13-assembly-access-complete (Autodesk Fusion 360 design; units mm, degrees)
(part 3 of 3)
extrude "Extrude2" cut sketch "E Rear Bearing Cap Bolt seed" profile of C1 along normal blind 3 (= "capThickness")
circular_pattern "C-Pattern1" TotalAngle 360
chamfer "Chamfer1" distance 0.3 (= "bedRelief")
work_plane "WorkPlane1" AlongDistance -29 (= "hubFace - adapterThickness") ExtraOffset 0
sketch "F Adapter Flange sketch" plane through (-20.5061, -20.5061, 0) normal (0.7071, 0.7071, 0) x axis (0, 0, 1)
  circle C1 centre (0, 0) radius 38
  dimension "d967" diameter C1 = 76 (= "mountOD")
extrude "Extrude1" new body sketch "F Adapter Flange sketch" along normal blind 6 (= "adapterThickness")
work_plane "WorkPlane2" AlongDistance -23 (= "hubFace") ExtraOffset 0
sketch "F Centering Pilot sketch" plane through (-16.2635, -16.2635, 0) normal (0.7071, 0.7071, 0) x axis (0, 0, 1)
  circle C1 centre (0, 0) radius 25
  circle C2 centre (0, 0) radius 17
  dimension "d972" diameter C1 = 50 (= "pilotDiameter")
  dimension "d973" diameter C2 = 34 (= "pilotInside")
extrude "Extrude2" add sketch "F Centering Pilot sketch" along normal blind 2 (= "pilotHeight")
work_plane "WorkPlane3" AlongDistance -29 (= "hubFace - adapterThickness") ExtraOffset 0
sketch "F Shaft Clearance sketch" plane through (-20.5061, -20.5061, 0) normal (0.7071, 0.7071, 0) x axis (0, 0, 1)
  circle C1 centre (0, 0) radius 4.25
  dimension "d978" diameter C1 = 8.5 (= "shaftClearance")
extrude "Extrude3" cut sketch "F Shaft Clearance sketch" along normal blind 6 (= "adapterThickness")
work_plane "WorkPlane4" AlongDistance -29 (= "hubFace - adapterThickness") ExtraOffset 0
sketch "F Mount Holes" plane through (-20.5061, -20.5061, 0) normal (0.7071, 0.7071, 0) x axis (0, 0, 1)
  circle C1 centre (22.6274, 22.6274) radius 2.15
  circle C2 centre (-22.6274, 22.6274) radius 2.15
  circle C3 centre (-22.6274, -22.6274) radius 2.15
  circle C4 centre (22.6274, -22.6274) radius 2.15
  point P1 (0, 0)
  point P2 (22.6274, 22.6274)
  point P3 (-22.6274, 22.6274)
  point P4 (-22.6274, -22.6274)
  point P5 (22.6274, -22.6274)
  dimension "d983" distance P1 P2 = 22.6274 (= "abs(mountCircle / ( 2 * sqrt(2) ))")
  dimension "d984" distance P1 P2 = 22.6274 (= "abs(mountCircle / ( 2 * sqrt(2) ))")
  dimension "d985" diameter C1 = 4.3 (= "m4Clearance")
  dimension "d986" distance P1 P3 = 22.6274 (= "abs(-mountCircle / ( 2 * sqrt(2) ))")
  dimension "d987" distance P1 P3 = 22.6274 (= "abs(mountCircle / ( 2 * sqrt(2) ))")
  dimension "d988" diameter C2 = 4.3 (= "m4Clearance")
  dimension "d989" distance P1 P4 = 22.6274 (= "abs(-mountCircle / ( 2 * sqrt(2) ))")
  dimension "d990" distance P1 P4 = 22.6274 (= "abs(-mountCircle / ( 2 * sqrt(2) ))")
  dimension "d991" diameter C3 = 4.3 (= "m4Clearance")
  dimension "d992" distance P1 P5 = 22.6274 (= "abs(mountCircle / ( 2 * sqrt(2) ))")
  dimension "d993" distance P1 P5 = 22.6274 (= "abs(-mountCircle / ( 2 * sqrt(2) ))")
  dimension "d994" diameter C4 = 4.3 (= "m4Clearance")
extrude "Extrude4" cut sketch "F Mount Holes" along normal blind 6 (= "adapterThickness")
sketch "F Compression Sleeve Holes" plane through (-20.5061, -20.5061, 0) normal (0.7071, 0.7071, 0) x axis (0, 0, 1)
  line L1 (11.3137, 0) -> (0, 0)
  line L2 (0, 11.3137) -> (0, 0)
  line L3 (-11.3137, 0) -> (0, 0)
  line L4 (0, -11.3137) -> (0, 0)
  circle C1 centre (11.3137, 0) radius 4.1
  circle C2 centre (0, 11.3137) radius 4.1
  circle C3 centre (-11.3137, 0) radius 4.1
  circle C4 centre (0, -11.3137) radius 4.1
  point P1 (0, 0)
  point P2 (11.3137, 0)
  point P3 (0, 11.3137)
  point P5 (0, -11.3137)
  horizontal L1
  vertical L2
  horizontal L3
  vertical L4
  dimension "d997" distance P1 P2 = 11.3137 (= "abs(hubHoleSpacing / sqrt(2))")
  dimension "d998" diameter C1 = 8.2 (= "sleeveOD + sleeveAllowance")
  dimension "d999" distance P1 P3 = 11.3137 (= "abs(hubHoleSpacing / sqrt(2))")
  dimension "d1000" diameter C2 = 8.2 (= "sleeveOD + sleeveAllowance")
  dimension "d59" = 150 (= "bodyWidth")
  dimension "d1002" diameter C3 = 8.2 (= "sleeveOD + sleeveAllowance")
  dimension "d1003" distance P1 P5 = 11.3137 (= "abs(-hubHoleSpacing / sqrt(2))")
  dimension "d1004" diameter C4 = 8.2 (= "sleeveOD + sleeveAllowance")
  dimension "d1001" distance = 11.3137 (= "abs(-hubHoleSpacing / sqrt(2))")
extrude "Extrude5" cut sketch "F Compression Sleeve Holes" profile of C1 C2 C3 C4 along normal blind 6 (= "adapterThickness")
chamfer "Chamfer1" distance 0.4 (= "entryChamfer")
chamfer "Chamfer2" distance 0.3 (= "bedRelief")
work_plane "WorkPlane1" AlongDistance 0.5 (= "qFront") ExtraOffset 0
sketch "Front 608 sketch" plane through (0.3536, 0.3536, 0) normal (0.7071, 0.7071, 0) x axis (0, 0, 1)
  circle C1 centre (0, 0) radius 11
  circle C2 centre (0, 0) radius 4
  dimension "d1011" diameter C1 = 22 (= "bearingOD")
  dimension "d1012" diameter C2 = 8 (= "bearingID")
extrude "Extrude1" new body sketch "Front 608 sketch" along normal blind 7 (= "bearingWidth")
work_plane "WorkPlane2" AlongDistance 25.6 (= "qRearBearing") ExtraOffset 0
sketch "Rear 608 sketch" plane through (18.1019, 18.1019, 0) normal (0.7071, 0.7071, 0) x axis (0, 0, 1)
  circle C1 centre (0, 0) radius 11
  circle C2 centre (0, 0) radius 4
  dimension "d1017" diameter C1 = 22 (= "bearingOD")
  dimension "d1018" diameter C2 = 8 (= "bearingID")
extrude "Extrude2" new body sketch "Rear 608 sketch" along normal blind 7 (= "bearingWidth")
work_plane "WorkPlane1" AlongDistance -24 ExtraOffset 0
sketch "Metal Shaft sketch" plane through (-16.9706, -16.9706, 0) normal (0.7071, 0.7071, 0) x axis (0, 0, 1)
  circle C1 centre (0, 0) radius 4
  dimension "d1023" diameter C1 = 8
extrude "Extrude1" new body sketch "Metal Shaft sketch" along normal blind 60
work_plane "WorkPlane1" AlongDistance -3.5 (= "qFront - 4 mm") ExtraOffset 0
sketch "Front Inner Ring Spacer sketch" plane through (-2.4749, -2.4749, 0) normal (0.7071, 0.7071, 0) x axis (0, 0, 1)
  circle C1 centre (0, 0) radius 5
  circle C2 centre (0, 0) radius 4
  dimension "d1028" diameter C1 = 10
  dimension "d1029" diameter C2 = 8
extrude "Extrude1" new body sketch "Front Inner Ring Spacer sketch" along normal blind 4
work_plane "WorkPlane2" AlongDistance 7.5 (= "qFront + bearingWidth") ExtraOffset 0
sketch "Rear Inner Ring Spacer sketch" plane through (5.3033, 5.3033, 0) normal (0.7071, 0.7071, 0) x axis (0, 0, 1)
  circle C1 centre (0, 0) radius 5
  circle C2 centre (0, 0) radius 4
  dimension "d1034" diameter C1 = 10
  dimension "d1035" diameter C2 = 8
extrude "Extrude2" new body sketch "Rear Inner Ring Spacer sketch" along normal blind 4
work_plane "WorkPlane1" AlongDistance -12.5 (= "qFront - 13 mm") ExtraOffset 0
sketch "Front Collar Maximum Envelope sketch" plane through (-8.8388, -8.8388, 0) normal (0.7071, 0.7071, 0) x axis (0, 0, 1)
  circle C1 centre (0, 0) radius 11.2
  circle C2 centre (0, 0) radius 4
  dimension "d1040" diameter C1 = 22.4
  dimension "d1041" diameter C2 = 8
extrude "Extrude1" new body sketch "Front Collar Maximum Envelope sketch" along normal blind 9
work_plane "WorkPlane2" AlongDistance 11.5 (= "qFront + bearingWidth + 4 mm") ExtraOffset 0
sketch "Rear Collar Maximum Envelope sketch" plane through (8.1317, 8.1317, 0) normal (0.7071, 0.7071, 0) x axis (0, 0, 1)
  circle C1 centre (0, 0) radius 11.2
  circle C2 centre (0, 0) radius 4
  dimension "d1046" diameter C1 = 22.4
  dimension "d1047" diameter C2 = 8
extrude "Extrude2" new body sketch "Rear Collar Maximum Envelope sketch" along normal blind 9
work_plane "WorkPlane1" AlongDistance 0 ExtraOffset 0
sketch "Spacer Pattern Axis" plane through (0, 0, 0) normal (0.7071, 0.7071, 0) x axis (0, 0, 1)
  circle C1 centre (0, 0) radius 0.5
  dimension "d1052" diameter C1 = 1
work_plane "WorkPlane2" AlongDistance 10.6 (= "qFrontBack") ExtraOffset 0
sketch "Support Spacer OD" plane through (7.4953, 7.4953, 0) normal (0.7071, 0.7071, 0) x axis (0, 0, 1)
  line L1 (17, 0) -> (0, 0)
  circle C1 centre (17, 0) radius 3
  circle C2 centre (17, 0) radius 1.6
  point P1 (0, 0)
  point P2 (17, 0)
  horizontal L1
  dimension "d1055" distance P1 P2 = 17 (= "supportCircle / 2")
  dimension "d1056" diameter C1 = 6 (= "supportSpacerOD")
  dimension "d1057" diameter C2 = 3.2
extrude "Extrude1" new body sketch "Support Spacer OD" profile of C1 C2 along normal blind 12 (= "supportSpacer")
circular_pattern "C-Pattern1" TotalAngle 360
work_plane "WorkPlane1" AlongDistance -29 (= "hubFace - adapterThickness") ExtraOffset 0
sketch "Sleeve 1 Outer" plane through (-20.5061, -20.5061, 0) normal (0.7071, 0.7071, 0) x axis (0, 0, 1)
  line L1 (11.3137, 0) -> (0, 0)
  circle C1 centre (11.3137, 0) radius 4
  circle C2 centre (11.3137, 0) radius 2.15
  point P1 (0, 0)
  point P2 (11.3137, 0)
  horizontal L1
  dimension "d1064" distance P1 P2 = 11.3137 (= "abs(hubHoleSpacing / sqrt(2))")
  dimension "d1065" diameter C1 = 8 (= "sleeveOD")
  dimension "d1066" diameter C2 = 4.3
extrude "Extrude1" new body sketch "Sleeve 1 Outer" profile of C1 C2 along normal blind 6 (= "adapterThickness")
work_plane "WorkPlane2" AlongDistance -29 (= "hubFace - adapterThickness") ExtraOffset 0
sketch "Sleeve 2 Outer" plane through (-20.5061, -20.5061, 0) normal (0.7071, 0.7071, 0) x axis (0, 0, 1)
  line L1 (0, 11.3137) -> (0, 0)
  circle C1 centre (0, 11.3137) radius 4
  circle C2 centre (0, 11.3137) radius 2.15
  point P1 (0, 0)
  point P2 (0, 11.3137)
  vertical L1
  dimension "d1071" distance P1 P2 = 11.3137 (= "abs(hubHoleSpacing / sqrt(2))")
  dimension "d1072" diameter C1 = 8 (= "sleeveOD")
  dimension "d1073" diameter C2 = 4.3
extrude "Extrude2" new body sketch "Sleeve 2 Outer" profile of C1 C2 along normal blind 6 (= "adapterThickness")
work_plane "WorkPlane3" AlongDistance -29 (= "hubFace - adapterThickness") ExtraOffset 0
sketch "Sleeve 3 Outer" plane through (-20.5061, -20.5061, 0) normal (0.7071, 0.7071, 0) x axis (0, 0, 1)
  line L1 (-11.3137, 0) -> (0, 0)
  circle C1 centre (-11.3137, 0) radius 4
  circle C2 centre (-11.3137, 0) radius 2.15
  point P1 (0, 0)
  point P2 (-11.3137, 0)
  horizontal L1
  dimension "d1078" distance P1 P2 = 11.3137 (= "abs(-hubHoleSpacing / sqrt(2))")
  dimension "d1079" diameter C1 = 8 (= "sleeveOD")
  dimension "d1080" diameter C2 = 4.3
extrude "Extrude3" new body sketch "Sleeve 3 Outer" profile of C1 C2 along normal blind 6 (= "adapterThickness")
work_plane "WorkPlane4" AlongDistance -29 (= "hubFace - adapterThickness") ExtraOffset 0
sketch "Sleeve 4 Outer" plane through (-20.5061, -20.5061, 0) normal (0.7071, 0.7071, 0) x axis (0, 0, 1)
  line L1 (0, -11.3137) -> (0, 0)
  circle C1 centre (0, -11.3137) radius 4
  circle C2 centre (0, -11.3137) radius 2.15
  point P1 (0, 0)
  point P2 (0, -11.3137)
  vertical L1
  dimension "d1085" distance P1 P2 = 11.3137 (= "abs(-hubHoleSpacing / sqrt(2))")
  dimension "d1086" diameter C1 = 8 (= "sleeveOD")
  dimension "d1087" diameter C2 = 4.3
extrude "Extrude4" new body sketch "Sleeve 4 Outer" profile of C1 C2 along normal blind 6 (= "adapterThickness")
work_plane "WorkPlane1" AlongDistance -23 (= "hubFace") ExtraOffset 0
sketch "Sonic Hub Body sketch" plane through (-16.2635, -16.2635, 0) normal (0.7071, 0.7071, 0) x axis (0, 0, 1)
  circle C1 centre (0, 0) radius 16
  circle C2 centre (0, 0) radius 4
  dimension "d1092" diameter C1 = 32
  dimension "d1093" diameter C2 = 8
extrude "Extrude1" new body sketch "Sonic Hub Body sketch" along normal blind 8
work_plane "WorkPlane2" AlongDistance -15 (= "hubFace + 8 mm") ExtraOffset 0
sketch "Sonic Hub Pilot sketch" plane through (-10.6066, -10.6066, 0) normal (0.7071, 0.7071, 0) x axis (0, 0, 1)
  circle C1 centre (0, 0) radius 7
  circle C2 centre (0, 0) radius 4
  dimension "d1098" diameter C1 = 14
  dimension "d1099" diameter C2 = 8
extrude "Extrude2" add sketch "Sonic Hub Pilot sketch" along normal blind 2
work_plane "WorkPlane3" AlongDistance -23 (= "hubFace") ExtraOffset 0
sketch "Hub M4 Thread Envelopes" plane through (-16.2635, -16.2635, 0) normal (0.7071, 0.7071, 0) x axis (0, 0, 1)
  line L1 (11.3137, 0) -> (0, 0)
  line L2 (0, 11.3137) -> (0, 0)
  line L3 (-11.3137, 0) -> (0, 0)
  line L4 (0, -11.3137) -> (0, 0)
  circle C1 centre (11.3137, 0) radius 2.15
  circle C2 centre (0, 11.3137) radius 2.15
  circle C3 centre (-11.3137, 0) radius 2.15
  circle C4 centre (0, -11.3137) radius 2.15
  point P1 (0, 0)
  point P2 (11.3137, 0)
  point P3 (0, 11.3137)
  point P5 (0, -11.3137)
  horizontal L1
  vertical L2
  horizontal L3
  vertical L4
  dimension "d1104" distance P1 P2 = 11.3137 (= "abs(hubHoleSpacing / sqrt(2))")
  dimension "d1105" diameter C1 = 4.3
  dimension "d1106" distance P1 P3 = 11.3137 (= "abs(hubHoleSpacing / sqrt(2))")
  dimension "d1107" diameter C2 = 4.3
  dimension "d59" = 150 (= "bodyWidth")
  dimension "d1109" diameter C3 = 4.3
  dimension "d1110" distance P1 P5 = 11.3137 (= "abs(-hubHoleSpacing / sqrt(2))")
  dimension "d1111" diameter C4 = 4.3
  dimension "d1108" distance = 11.3137 (= "abs(-hubHoleSpacing / sqrt(2))")
extrude "Extrude3" cut sketch "Hub M4 Thread Envelopes" profile of C1 C2 C3 C4 along normal blind 8
work_plane "WorkPlane1" AlongDistance -30 (= "hubFace - adapterThickness - 1 mm") ExtraOffset 0
sketch "Hub Screw 1 Profile" plane through (-21.2132, -21.2132, 0) normal (0.7071, 0.7071, 0) x axis (0, 0, 1)
  line L1 (11.3137, 0) -> (0, 0)
  circle C1 centre (11.3137, 0) radius 2
  point P1 (0, 0)
  point P2 (11.3137, 0)
  horizontal L1
  dimension "d1116" distance P1 P2 = 11.3137 (= "abs(hubHoleSpacing / sqrt(2))")
  dimension "d1117" diameter C1 = 4
extrude "Extrude1" new body sketch "Hub Screw 1 Profile" profile of C1 along normal blind 12
work_plane "WorkPlane2" AlongDistance -34 (= "hubFace - adapterThickness - 5 mm") ExtraOffset 0
sketch "Hub Screw Head 1 Profile" plane through (-24.0416, -24.0416, 0) normal (0.7071, 0.7071, 0) x axis (0, 0, 1)
  line L1 (11.3137, 0) -> (0, 0)
  circle C1 centre (11.3137, 0) radius 3.5
  point P1 (0, 0)
  point P2 (11.3137, 0)
  horizontal L1
  dimension "d1122" distance P1 P2 = 11.3137 (= "abs(hubHoleSpacing / sqrt(2))")
  dimension "d1123" diameter C1 = 7
extrude "Extrude2" new body sketch "Hub Screw Head 1 Profile" profile of C1 along normal blind 4
work_plane "WorkPlane3" AlongDistance -30 (= "hubFace - adapterThickness - 1 mm") ExtraOffset 0
sketch "Hub Washer 1 Outer" plane through (-21.2132, -21.2132, 0) normal (0.7071, 0.7071, 0) x axis (0, 0, 1)
  line L1 (11.3137, 0) -> (0, 0)
  circle C1 centre (11.3137, 0) radius 6
  circle C2 centre (11.3137, 0) radius 2.15
  point P1 (0, 0)
  point P2 (11.3137, 0)
  horizontal L1
  dimension "d1128" distance P1 P2 = 11.3137 (= "abs(hubHoleSpacing / sqrt(2))")
  dimension "d1129" diameter C1 = 12
  dimension "d1130" diameter C2 = 4.3
extrude "Extrude3" new body sketch "Hub Washer 1 Outer" profile of C1 C2 along normal blind 1
work_plane "WorkPlane4" AlongDistance -30 (= "hubFace - adapterThickness - 1 mm") ExtraOffset 0
sketch "Hub Screw 2 Profile" plane through (-21.2132, -21.2132, 0) normal (0.7071, 0.7071, 0) x axis (0, 0, 1)
  line L1 (0, 11.3137) -> (0, 0)
  circle C1 centre (0, 11.3137) radius 2
  point P1 (0, 0)
  point P2 (0, 11.3137)
  vertical L1
  dimension "d1135" distance P1 P2 = 11.3137 (= "abs(hubHoleSpacing / sqrt(2))")
  dimension "d1136" diameter C1 = 4
extrude "Extrude4" new body sketch "Hub Screw 2 Profile" profile of C1 along normal blind 12
work_plane "WorkPlane5" AlongDistance -34 (= "hubFace - adapterThickness - 5 mm") ExtraOffset 0
sketch "Hub Screw Head 2 Profile" plane through (-24.0416, -24.0416, 0) normal (0.7071, 0.7071, 0) x axis (0, 0, 1)
  line L1 (0, 11.3137) -> (0, 0)
  circle C1 centre (0, 11.3137) radius 3.5
  point P1 (0, 0)
  point P2 (0, 11.3137)
  vertical L1
  dimension "d1141" distance P1 P2 = 11.3137 (= "abs(hubHoleSpacing / sqrt(2))")
  dimension "d1142" diameter C1 = 7
extrude "Extrude5" new body sketch "Hub Screw Head 2 Profile" profile of C1 along normal blind 4
work_plane "WorkPlane6" AlongDistance -30 (= "hubFace - adapterThickness - 1 mm") ExtraOffset 0
sketch "Hub Washer 2 Outer" plane through (-21.2132, -21.2132, 0) normal (0.7071, 0.7071, 0) x axis (0, 0, 1)
  line L1 (0, 11.3137) -> (0, 0)
  circle C1 centre (0, 11.3137) radius 6
  circle C2 centre (0, 11.3137) radius 2.15
  point P1 (0, 0)
  point P2 (0, 11.3137)
  vertical L1
  dimension "d1147" distance P1 P2 = 11.3137 (= "abs(hubHoleSpacing / sqrt(2))")
  dimension "d1148" diameter C1 = 12
  dimension "d1149" diameter C2 = 4.3
extrude "Extrude6" new body sketch "Hub Washer 2 Outer" profile of C1 C2 along normal blind 1
work_plane "WorkPlane7" AlongDistance -30 (= "hubFace - adapterThickness - 1 mm") ExtraOffset 0
sketch "Hub Screw 3 Profile" plane through (-21.2132, -21.2132, 0) normal (0.7071, 0.7071, 0) x axis (0, 0, 1)
  line L1 (-11.3137, 0) -> (0, 0)
  circle C1 centre (-11.3137, 0) radius 2
  point P1 (0, 0)
  point P2 (-11.3137, 0)
  horizontal L1
  dimension "d1154" distance P1 P2 = 11.3137 (= "abs(-hubHoleSpacing / sqrt(2))")
  dimension "d1155" diameter C1 = 4
extrude "Extrude7" new body sketch "Hub Screw 3 Profile" profile of C1 along normal blind 12
work_plane "WorkPlane8" AlongDistance -34 (= "hubFace - adapterThickness - 5 mm") ExtraOffset 0
sketch "Hub Screw Head 3 Profile" plane through (-24.0416, -24.0416, 0) normal (0.7071, 0.7071, 0) x axis (0, 0, 1)
  line L1 (-11.3137, 0) -> (0, 0)
  circle C1 centre (-11.3137, 0) radius 3.5
  point P1 (0, 0)
  point P2 (-11.3137, 0)
  horizontal L1
  dimension "d1160" distance P1 P2 = 11.3137 (= "abs(-hubHoleSpacing / sqrt(2))")
  dimension "d1161" diameter C1 = 7
extrude "Extrude8" new body sketch "Hub Screw Head 3 Profile" profile of C1 along normal blind 4
work_plane "WorkPlane9" AlongDistance -30 (= "hubFace - adapterThickness - 1 mm") ExtraOffset 0
sketch "Hub Washer 3 Outer" plane through (-21.2132, -21.2132, 0) normal (0.7071, 0.7071, 0) x axis (0, 0, 1)
  line L1 (-11.3137, 0) -> (0, 0)
  circle C1 centre (-11.3137, 0) radius 6
  circle C2 centre (-11.3137, 0) radius 2.15
  point P1 (0, 0)
  point P2 (-11.3137, 0)
  horizontal L1
  dimension "d1166" distance P1 P2 = 11.3137 (= "abs(-hubHoleSpacing / sqrt(2))")
  dimension "d1167" diameter C1 = 12
  dimension "d1168" diameter C2 = 4.3
extrude "Extrude9" new body sketch "Hub Washer 3 Outer" profile of C1 C2 along normal blind 1
work_plane "WorkPlane10" AlongDistance -30 (= "hubFace - adapterThickness - 1 mm") ExtraOffset 0
sketch "Hub Screw 4 Profile" plane through (-21.2132, -21.2132, 0) normal (0.7071, 0.7071, 0) x axis (0, 0, 1)
  line L1 (0, -11.3137) -> (0, 0)
  circle C1 centre (0, -11.3137) radius 2
  point P1 (0, 0)
  point P2 (0, -11.3137)
  vertical L1
  dimension "d1173" distance P1 P2 = 11.3137 (= "abs(-hubHoleSpacing / sqrt(2))")
  dimension "d1174" diameter C1 = 4
extrude "Extrude10" new body sketch "Hub Screw 4 Profile" profile of C1 along normal blind 12
work_plane "WorkPlane11" AlongDistance -34 (= "hubFace - adapterThickness - 5 mm") ExtraOffset 0
sketch "Hub Screw Head 4 Profile" plane through (-24.0416, -24.0416, 0) normal (0.7071, 0.7071, 0) x axis (0, 0, 1)
  line L1 (0, -11.3137) -> (0, 0)
  circle C1 centre (0, -11.3137) radius 3.5
  point P1 (0, 0)
  point P2 (0, -11.3137)
  vertical L1
  dimension "d1179" distance P1 P2 = 11.3137 (= "abs(-hubHoleSpacing / sqrt(2))")
  dimension "d1180" diameter C1 = 7
extrude "Extrude11" new body sketch "Hub Screw Head 4 Profile" profile of C1 along normal blind 4
work_plane "WorkPlane12" AlongDistance -30 (= "hubFace - adapterThickness - 1 mm") ExtraOffset 0
sketch "Hub Washer 4 Outer" plane through (-21.2132, -21.2132, 0) normal (0.7071, 0.7071, 0) x axis (0, 0, 1)
  line L1 (0, -11.3137) -> (0, 0)
  circle C1 centre (0, -11.3137) radius 6
  circle C2 centre (0, -11.3137) radius 2.15
  point P1 (0, 0)
  point P2 (0, -11.3137)
  vertical L1
  dimension "d1185" distance P1 P2 = 11.3137 (= "abs(-hubHoleSpacing / sqrt(2))")
  dimension "d1186" diameter C1 = 12
  dimension "d1187" diameter C2 = 4.3
extrude "Extrude12" new body sketch "Hub Washer 4 Outer" profile of C1 C2 along normal blind 1
work_plane "WorkPlane1" AlongDistance -30 (= "hubFace - adapterThickness - 1 mm") ExtraOffset 0
sketch "Adapter Screw 1 Profile" plane through (-21.2132, -21.2132, 0) normal (0.7071, 0.7071, 0) x axis (0, 0, 1)
  circle C1 centre (22.6274, 22.6274) radius 2
  point P1 (0, 0)
  point P2 (22.6274, 22.6274)
  dimension "d1192" distance P1 P2 = 22.6274 (= "abs(mountCircle / ( 2 * sqrt(2) ))")
  dimension "d1193" distance P1 P2 = 22.6274 (= "abs(mountCircle / ( 2 * sqrt(2) ))")
  dimension "d1194" diameter C1 = 4
extrude "Extrude1" new body sketch "Adapter Screw 1 Profile" along normal blind 30
work_plane "WorkPlane2" AlongDistance -34 (= "hubFace - adapterThickness - 5 mm") ExtraOffset 0
sketch "Adapter Screw Head 1 Profile" plane through (-24.0416, -24.0416, 0) normal (0.7071, 0.7071, 0) x axis (0, 0, 1)
  circle C1 centre (22.6274, 22.6274) radius 3.5
  point P1 (0, 0)
  point P2 (22.6274, 22.6274)
  dimension "d1199" distance P1 P2 = 22.6274 (= "abs(mountCircle / ( 2 * sqrt(2) ))")
  dimension "d1200" distance P1 P2 = 22.6274 (= "abs(mountCircle / ( 2 * sqrt(2) ))")
  dimension "d1201" diameter C1 = 7
extrude "Extrude2" new body sketch "Adapter Screw Head 1 Profile" along normal blind 4
work_plane "WorkPlane3" AlongDistance -30 (= "hubFace - adapterThickness - 1 mm") ExtraOffset 0
sketch "Adapter Washer 1 Outer" plane through (-21.2132, -21.2132, 0) normal (0.7071, 0.7071, 0) x axis (0, 0, 1)
  circle C1 centre (22.6274, 22.6274) radius 4.5
  circle C2 centre (22.6274, 22.6274) radius 2.15
  point P1 (0, 0)
  point P2 (22.6274, 22.6274)
  dimension "d1206" distance P1 P2 = 22.6274 (= "abs(mountCircle / ( 2 * sqrt(2) ))")
  dimension "d1207" distance P1 P2 = 22.6274 (= "abs(mountCircle / ( 2 * sqrt(2) ))")
  dimension "d1208" diameter C1 = 9
  dimension "d1209" diameter C2 = 4.3
extrude "Extrude3" new body sketch "Adapter Washer 1 Outer" along normal blind 1
work_plane "WorkPlane4" ExtraOffset 0
sketch "Adapter Nut Hex 1" plane through (-3.182, -3.182, 0) normal (0.7071, 0.7071, 0) x axis (0, 0, 1)
  line L1 (24.6481, 26.1274) -> (26.6689, 22.6274)
  line L2 (20.6067, 26.1274) -> (24.6481, 26.1274)
  line L3 (18.586, 22.6274) -> (20.6067, 26.1274)
  line L4 (20.6067, 19.1274) -> (18.586, 22.6274)
  line L5 (24.6481, 19.1274) -> (20.6067, 19.1274)
  line L6 (26.6689, 22.6274) -> (24.6481, 19.1274)
  circle C1 centre (22.6274, 22.6274) radius 4.0415
  point P3 (26.6689, 22.6274)
  point P4 (24.6481, 26.1274)
  point P5 (20.6067, 26.1274)
  point P6 (18.586, 22.6274)
  point P7 (20.6067, 19.1274)
  point P8 (24.6481, 19.1274)
  point P1 (0, 0)
  point P2 (22.6274, 22.6274)
  coincident C1 P3
  coincident C1 P4
  coincident C1 P5
  coincident C1 P6
  coincident C1 P7
  coincident C1 P8
  equal L1 L2
  equal L1 L3
  equal L1 L4
  equal L1 L5
  equal L1 L6
  horizontal L2
  dimension "d1214" distance P1 P2 = 22.6274 (= "abs(mountCircle / ( 2 * sqrt(2) ))")
  dimension "d1215" distance P1 P2 = 22.6274 (= "abs(mountCircle / ( 2 * sqrt(2) ))")
  dimension "d1216" diameter C1 = 8.0829 (= "2 * ( 7 mm ) / sqrt(3)")
extrude "Extrude4" new body sketch "Adapter Nut Hex 1" profile of L1 L2 L3 L4 L5 L6 along normal blind 3.2
sketch "Nut Thread Clearance 1" plane through (-3.182, -3.182, 0) normal (0.7071, 0.7071, 0) x axis (0, 0, 1)
  circle C1 centre (22.6274, 22.6274) radius 2.15
  point P1 (0, 0)
  point P2 (22.6274, 22.6274)
  dimension "d1219" distance P1 P2 = 22.6274 (= "abs(mountCircle / ( 2 * sqrt(2) ))")
  dimension "d1220" distance P1 P2 = 22.6274 (= "abs(mountCircle / ( 2 * sqrt(2) ))")
  dimension "d1221" diameter C1 = 4.3
extrude "Extrude5" cut sketch "Nut Thread Clearance 1" along normal blind 3.2
work_plane "WorkPlane5" AlongDistance -30 (= "hubFace - adapterThickness - 1 mm") ExtraOffset 0
sketch "Adapter Screw 2 Profile" plane through (-21.2132, -21.2132, 0) normal (0.7071, 0.7071, 0) x axis (0, 0, 1)
  circle C1 centre (-22.6274, 22.6274) radius 2
  point P1 (0, 0)
  point P2 (-22.6274, 22.6274)
  dimension "d1226" distance P1 P2 = 22.6274 (= "abs(-mountCircle / ( 2 * sqrt(2) ))")
  dimension "d1227" distance P1 P2 = 22.6274 (= "abs(mountCircle / ( 2 * sqrt(2) ))")
  dimension "d1228" diameter C1 = 4
extrude "Extrude6" new body sketch "Adapter Screw 2 Profile" along normal blind 30
work_plane "WorkPlane6" AlongDistance -34 (= "hubFace - adapterThickness - 5 mm") ExtraOffset 0
sketch "Adapter Screw Head 2 Profile" plane through (-24.0416, -24.0416, 0) normal (0.7071, 0.7071, 0) x axis (0, 0, 1)
  circle C1 centre (-22.6274, 22.6274) radius 3.5
  point P1 (0, 0)
  point P2 (-22.6274, 22.6274)
  dimension "d1233" distance P1 P2 = 22.6274 (= "abs(-mountCircle / ( 2 * sqrt(2) ))")
  dimension "d1234" distance P1 P2 = 22.6274 (= "abs(mountCircle / ( 2 * sqrt(2) ))")
  dimension "d1235" diameter C1 = 7
extrude "Extrude7" new body sketch "Adapter Screw Head 2 Profile" along normal blind 4
work_plane "WorkPlane7" AlongDistance -30 (= "hubFace - adapterThickness - 1 mm") ExtraOffset 0
sketch "Adapter Washer 2 Outer" plane through (-21.2132, -21.2132, 0) normal (0.7071, 0.7071, 0) x axis (0, 0, 1)
  circle C1 centre (-22.6274, 22.6274) radius 4.5
  circle C2 centre (-22.6274, 22.6274) radius 2.15
  point P1 (0, 0)
  point P2 (-22.6274, 22.6274)
  dimension "d1240" distance P1 P2 = 22.6274 (= "abs(-mountCircle / ( 2 * sqrt(2) ))")
  dimension "d1241" distance P1 P2 = 22.6274 (= "abs(mountCircle / ( 2 * sqrt(2) ))")
  dimension "d1242" diameter C1 = 9
  dimension "d1243" diameter C2 = 4.3
extrude "Extrude8" new body sketch "Adapter Washer 2 Outer" along normal blind 1
work_plane "WorkPlane8" ExtraOffset 0
sketch "Adapter Nut Hex 2" plane through (-3.182, -3.182, 0) normal (0.7071, 0.7071, 0) x axis (0, 0, 1)
  line L1 (-20.6067, 26.1274) -> (-18.586, 22.6274)
  line L2 (-24.6481, 26.1274) -> (-20.6067, 26.1274)
  line L3 (-26.6689, 22.6274) -> (-24.6481, 26.1274)
  line L4 (-24.6481, 19.1274) -> (-26.6689, 22.6274)
  line L5 (-20.6067, 19.1274) -> (-24.6481, 19.1274)
  line L6 (-18.586, 22.6274) -> (-20.6067, 19.1274)
  circle C1 centre (-22.6274, 22.6274) radius 4.0415
  point P3 (-18.586, 22.6274)
  point P4 (-20.6067, 26.1274)
  point P5 (-24.6481, 26.1274)
  point P6 (-26.6689, 22.6274)
  point P7 (-24.6481, 19.1274)
  point P8 (-20.6067, 19.1274)
  point P1 (0, 0)
  point P2 (-22.6274, 22.6274)
  coincident C1 P3
  coincident C1 P4
  coincident C1 P5
  coincident C1 P6
  coincident C1 P7
  coincident C1 P8
  equal L1 L2
  equal L1 L3
  equal L1 L4
  equal L1 L5
  equal L1 L6
  horizontal L2
  dimension "d1248" distance P1 P2 = 22.6274 (= "abs(-mountCircle / ( 2 * sqrt(2) ))")
  dimension "d1249" distance P1 P2 = 22.6274 (= "abs(mountCircle / ( 2 * sqrt(2) ))")
  dimension "d1250" diameter C1 = 8.0829 (= "2 * ( 7 mm ) / sqrt(3)")
extrude "Extrude9" new body sketch "Adapter Nut Hex 2" profile of L1 L2 L3 L4 L5 L6 along normal blind 3.2
sketch "Nut Thread Clearance 2" plane through (-3.182, -3.182, 0) normal (0.7071, 0.7071, 0) x axis (0, 0, 1)
  circle C1 centre (-22.6274, 22.6274) radius 2.15
  point P1 (0, 0)
  point P2 (-22.6274, 22.6274)
  dimension "d1253" distance P1 P2 = 22.6274 (= "abs(-mountCircle / ( 2 * sqrt(2) ))")
  dimension "d1254" distance P1 P2 = 22.6274 (= "abs(mountCircle / ( 2 * sqrt(2) ))")
  dimension "d1255" diameter C1 = 4.3
extrude "Extrude10" cut sketch "Nut Thread Clearance 2" along normal blind 3.2
work_plane "WorkPlane9" AlongDistance -30 (= "hubFace - adapterThickness - 1 mm") ExtraOffset 0
sketch "Adapter Screw 3 Profile" plane through (-21.2132, -21.2132, 0) normal (0.7071, 0.7071, 0) x axis (0, 0, 1)
  circle C1 centre (-22.6274, -22.6274) radius 2
  point P1 (0, 0)
  point P2 (-22.6274, -22.6274)
  dimension "d1260" distance P1 P2 = 22.6274 (= "abs(-mountCircle / ( 2 * sqrt(2) ))")
  dimension "d1261" distance P1 P2 = 22.6274 (= "abs(-mountCircle / ( 2 * sqrt(2) ))")
  dimension "d1262" diameter C1 = 4
extrude "Extrude11" new body sketch "Adapter Screw 3 Profile" along normal blind 30
work_plane "WorkPlane10" AlongDistance -34 (= "hubFace - adapterThickness - 5 mm") ExtraOffset 0
sketch "Adapter Screw Head 3 Profile" plane through (-24.0416, -24.0416, 0) normal (0.7071, 0.7071, 0) x axis (0, 0, 1)
  circle C1 centre (-22.6274, -22.6274) radius 3.5
  point P1 (0, 0)
  point P2 (-22.6274, -22.6274)
  dimension "d1267" distance P1 P2 = 22.6274 (= "abs(-mountCircle / ( 2 * sqrt(2) ))")
  dimension "d1268" distance P1 P2 = 22.6274 (= "abs(-mountCircle / ( 2 * sqrt(2) ))")
  dimension "d1269" diameter C1 = 7
extrude "Extrude12" new body sketch "Adapter Screw Head 3 Profile" along normal blind 4
work_plane "WorkPlane11" AlongDistance -30 (= "hubFace - adapterThickness - 1 mm") ExtraOffset 0
sketch "Adapter Washer 3 Outer" plane through (-21.2132, -21.2132, 0) normal (0.7071, 0.7071, 0) x axis (0, 0, 1)
  circle C1 centre (-22.6274, -22.6274) radius 4.5
  circle C2 centre (-22.6274, -22.6274) radius 2.15
  point P1 (0, 0)
  point P2 (-22.6274, -22.6274)
  dimension "d1274" distance P1 P2 = 22.6274 (= "abs(-mountCircle / ( 2 * sqrt(2) ))")
  dimension "d1275" distance P1 P2 = 22.6274 (= "abs(-mountCircle / ( 2 * sqrt(2) ))")
  dimension "d1276" diameter C1 = 9
  dimension "d1277" diameter C2 = 4.3
extrude "Extrude13" new body sketch "Adapter Washer 3 Outer" along normal blind 1
work_plane "WorkPlane12" ExtraOffset 0
sketch "Adapter Nut Hex 3" plane through (-3.182, -3.182, 0) normal (0.7071, 0.7071, 0) x axis (0, 0, 1)
  line L1 (-20.6067, -19.1274) -> (-18.586, -22.6274)
  line L2 (-24.6481, -19.1274) -> (-20.6067, -19.1274)
  line L3 (-26.6689, -22.6274) -> (-24.6481, -19.1274)
  line L4 (-24.6481, -26.1274) -> (-26.6689, -22.6274)
  line L5 (-20.6067, -26.1274) -> (-24.6481, -26.1274)
  line L6 (-18.586, -22.6274) -> (-20.6067, -26.1274)
  circle C1 centre (-22.6274, -22.6274) radius 4.0415
  point P3 (-18.586, -22.6274)
  point P4 (-20.6067, -19.1274)
  point P5 (-24.6481, -19.1274)
  point P6 (-26.6689, -22.6274)
  point P7 (-24.6481, -26.1274)
  point P8 (-20.6067, -26.1274)
  point P1 (0, 0)
  point P2 (-22.6274, -22.6274)
  coincident C1 P3
  coincident C1 P4
  coincident C1 P5
  coincident C1 P6
  coincident C1 P7
  coincident C1 P8
  equal L1 L2
  equal L1 L3
  equal L1 L4
  equal L1 L5
  equal L1 L6
  horizontal L2
  dimension "d1282" distance P1 P2 = 22.6274 (= "abs(-mountCircle / ( 2 * sqrt(2) ))")
  dimension "d1283" distance P1 P2 = 22.6274 (= "abs(-mountCircle / ( 2 * sqrt(2) ))")
  dimension "d1284" diameter C1 = 8.0829 (= "2 * ( 7 mm ) / sqrt(3)")
extrude "Extrude14" new body sketch "Adapter Nut Hex 3" profile of L1 L2 L3 L4 L5 L6 along normal blind 3.2
sketch "Nut Thread Clearance 3" plane through (-3.182, -3.182, 0) normal (0.7071, 0.7071, 0) x axis (0, 0, 1)
  circle C1 centre (-22.6274, -22.6274) radius 2.15
  point P1 (0, 0)
  point P2 (-22.6274, -22.6274)
  dimension "d1287" distance P1 P2 = 22.6274 (= "abs(-mountCircle / ( 2 * sqrt(2) ))")
  dimension "d1288" distance P1 P2 = 22.6274 (= "abs(-mountCircle / ( 2 * sqrt(2) ))")
  dimension "d1289" diameter C1 = 4.3
extrude "Extrude15" cut sketch "Nut Thread Clearance 3" along normal blind 3.2
work_plane "WorkPlane13" AlongDistance -30 (= "hubFace - adapterThickness - 1 mm") ExtraOffset 0
sketch "Adapter Screw 4 Profile" plane through (-21.2132, -21.2132, 0) normal (0.7071, 0.7071, 0) x axis (0, 0, 1)
  circle C1 centre (22.6274, -22.6274) radius 2
  point P1 (0, 0)
  point P2 (22.6274, -22.6274)
  dimension "d1294" distance P1 P2 = 22.6274 (= "abs(mountCircle / ( 2 * sqrt(2) ))")
  dimension "d1295" distance P1 P2 = 22.6274 (= "abs(-mountCircle / ( 2 * sqrt(2) ))")
  dimension "d1296" diameter C1 = 4
extrude "Extrude16" new body sketch "Adapter Screw 4 Profile" along normal blind 30
work_plane "WorkPlane14" AlongDistance -34 (= "hubFace - adapterThickness - 5 mm") ExtraOffset 0
sketch "Adapter Screw Head 4 Profile" plane through (-24.0416, -24.0416, 0) normal (0.7071, 0.7071, 0) x axis (0, 0, 1)
  circle C1 centre (22.6274, -22.6274) radius 3.5
  point P1 (0, 0)
  point P2 (22.6274, -22.6274)
  dimension "d1301" distance P1 P2 = 22.6274 (= "abs(mountCircle / ( 2 * sqrt(2) ))")
  dimension "d1302" distance P1 P2 = 22.6274 (= "abs(-mountCircle / ( 2 * sqrt(2) ))")
  dimension "d1303" diameter C1 = 7
extrude "Extrude17" new body sketch "Adapter Screw Head 4 Profile" along normal blind 4
work_plane "WorkPlane15" AlongDistance -30 (= "hubFace - adapterThickness - 1 mm") ExtraOffset 0
sketch "Adapter Washer 4 Outer" plane through (-21.2132, -21.2132, 0) normal (0.7071, 0.7071, 0) x axis (0, 0, 1)
  circle C1 centre (22.6274, -22.6274) radius 4.5
  circle C2 centre (22.6274, -22.6274) radius 2.15
  point P1 (0, 0)
  point P2 (22.6274, -22.6274)
  dimension "d1308" distance P1 P2 = 22.6274 (= "abs(mountCircle / ( 2 * sqrt(2) ))")
  dimension "d1309" distance P1 P2 = 22.6274 (= "abs(-mountCircle / ( 2 * sqrt(2) ))")
  dimension "d1310" diameter C1 = 9
  dimension "d1311" diameter C2 = 4.3
extrude "Extrude18" new body sketch "Adapter Washer 4 Outer" along normal blind 1
work_plane "WorkPlane16" ExtraOffset 0
sketch "Adapter Nut Hex 4" plane through (-3.182, -3.182, 0) normal (0.7071, 0.7071, 0) x axis (0, 0, 1)
  line L1 (24.6481, -19.1274) -> (26.6689, -22.6274)
  line L2 (20.6067, -19.1274) -> (24.6481, -19.1274)
  line L3 (18.586, -22.6274) -> (20.6067, -19.1274)
  line L4 (20.6067, -26.1274) -> (18.586, -22.6274)
  line L5 (24.6481, -26.1274) -> (20.6067, -26.1274)
  line L6 (26.6689, -22.6274) -> (24.6481, -26.1274)
  circle C1 centre (22.6274, -22.6274) radius 4.0415
  point P3 (26.6689, -22.6274)
  point P4 (24.6481, -19.1274)
  point P5 (20.6067, -19.1274)
  point P6 (18.586, -22.6274)
  point P7 (20.6067, -26.1274)
  point P8 (24.6481, -26.1274)
  point P1 (0, 0)
  point P2 (22.6274, -22.6274)
  coincident C1 P3
  coincident C1 P4
  coincident C1 P5
  coincident C1 P6
  coincident C1 P7
  coincident C1 P8
  equal L1 L2
  equal L1 L3
  equal L1 L4
  equal L1 L5
  equal L1 L6
  horizontal L2
  dimension "d1316" distance P1 P2 = 22.6274 (= "abs(mountCircle / ( 2 * sqrt(2) ))")
  dimension "d1317" distance P1 P2 = 22.6274 (= "abs(-mountCircle / ( 2 * sqrt(2) ))")
  dimension "d1318" diameter C1 = 8.0829 (= "2 * ( 7 mm ) / sqrt(3)")
extrude "Extrude19" new body sketch "Adapter Nut Hex 4" profile of L1 L2 L3 L4 L5 L6 along normal blind 3.2
sketch "Nut Thread Clearance 4" plane through (-3.182, -3.182, 0) normal (0.7071, 0.7071, 0) x axis (0, 0, 1)
  circle C1 centre (22.6274, -22.6274) radius 2.15
  point P1 (0, 0)
  point P2 (22.6274, -22.6274)
  dimension "d1321" distance P1 P2 = 22.6274 (= "abs(mountCircle / ( 2 * sqrt(2) ))")
  dimension "d1322" distance P1 P2 = 22.6274 (= "abs(-mountCircle / ( 2 * sqrt(2) ))")
  dimension "d1323" diameter C1 = 4.3
extrude "Extrude20" cut sketch "Nut Thread Clearance 4" along normal blind 3.2
work_plane "WorkPlane1" AlongDistance 0 ExtraOffset 0
sketch "M3 Pattern Axis" plane through (0, 0, 0) normal (0.7071, 0.7071, 0) x axis (0, 0, 1)
  circle C1 centre (0, 0) radius 0.5
  dimension "d1328" diameter C1 = 1
work_plane "WorkPlane2" AlongDistance -8.7 (= "qRearEnd + capThickness + 0.5 mm - 45 mm") ExtraOffset 0
sketch "M3 Shank Profile" plane through (-6.1518, -6.1518, 0) normal (0.7071, 0.7071, 0) x axis (0, 0, 1)
  line L1 (17, 0) -> (0, 0)
  circle C1 centre (17, 0) radius 1.5
  point P1 (0, 0)
  point P2 (17, 0)
  horizontal L1
  dimension "d1331" distance P1 P2 = 17 (= "supportCircle / 2")
  dimension "d1332" diameter C1 = 3
extrude "Extrude1" new body sketch "M3 Shank Profile" profile of C1 along normal blind 45
work_plane "WorkPlane3" AlongDistance 36.3 (= "qRearEnd + capThickness + 0.5 mm") ExtraOffset 0
sketch "M3 Head Profile" plane through (25.668, 25.668, 0) normal (0.7071, 0.7071, 0) x axis (0, 0, 1)
  line L1 (17, 0) -> (0, 0)
  circle C1 centre (17, 0) radius 2.75
  point P1 (0, 0)
  point P2 (17, 0)
  horizontal L1
  dimension "d1337" distance P1 P2 = 17 (= "supportCircle / 2")
  dimension "d1338" diameter C1 = 5.5
extrude "Extrude2" new body sketch "M3 Head Profile" profile of C1 along normal blind 3
work_plane "WorkPlane4" AlongDistance 35.8 (= "qRearEnd + capThickness") ExtraOffset 0
sketch "Rear M3 Washer Profile" plane through (25.3144, 25.3144, 0) normal (0.7071, 0.7071, 0) x axis (0, 0, 1)
  line L1 (17, 0) -> (0, 0)
  circle C1 centre (17, 0) radius 3.5
  circle C2 centre (17, 0) radius 1.65
  point P1 (0, 0)
  point P2 (17, 0)
  horizontal L1
  dimension "d1343" distance P1 P2 = 17 (= "supportCircle / 2")
  dimension "d1344" diameter C1 = 7
  dimension "d1345" diameter C2 = 3.3
extrude "Extrude3" new body sketch "Rear M3 Washer Profile" profile of C1 C2 along normal blind 0.5
work_plane "WorkPlane5" AlongDistance -3 (= "qFront - capThickness - 0.5 mm") ExtraOffset 0
sketch "Front M3 Washer Profile" plane through (-2.1213, -2.1213, 0) normal (0.7071, 0.7071, 0) x axis (0, 0, 1)
  line L1 (17, 0) -> (0, 0)
  circle C1 centre (17, 0) radius 3.5
  circle C2 centre (17, 0) radius 1.65
  point P1 (0, 0)
  point P2 (17, 0)
  horizontal L1
  dimension "d1350" distance P1 P2 = 17 (= "supportCircle / 2")
  dimension "d1351" diameter C1 = 7
  dimension "d1352" diameter C2 = 3.3
extrude "Extrude4" new body sketch "Front M3 Washer Profile" profile of C1 C2 along normal blind 0.5
work_plane "WorkPlane6" AlongDistance -7 (= "qFront - capThickness - 4.5 mm") ExtraOffset 0
sketch "Front M3 Nyloc Envelope Profile" plane through (-4.9497, -4.9497, 0) normal (0.7071, 0.7071, 0) x axis (0, 0, 1)
  line L1 (17, 0) -> (0, 0)
  circle C1 centre (17, 0) radius 3.18
  circle C2 centre (17, 0) radius 1.65
  point P1 (0, 0)
  point P2 (17, 0)
  horizontal L1
  dimension "d1357" distance P1 P2 = 17 (= "supportCircle / 2")
  dimension "d1358" diameter C1 = 6.36
  dimension "d1359" diameter C2 = 3.3
extrude "Extrude5" new body sketch "Front M3 Nyloc Envelope Profile" profile of C1 C2 along normal blind 4
circular_pattern "C-Pattern1" TotalAngle 360
work_plane "WorkPlane25" RotateAngle 90 ExtraOffset 0
work_plane "WorkPlane26" AlongDistance 75 (= "bodyWidth / 2") ExtraOffset 0
work_plane "WorkPlane27" AlongDistance -35 ExtraOffset 0
ground "Pin"
as_built_joint "As-built1" RotateMinimum 0 RotateMaximum 180
as_built_joint "As-built2"
as_built_joint "As-built3"
as_built_joint "As-built4"
as_built_joint "As-built5"
as_built_joint "As-built6"
as_built_joint "As-built7"
as_built_joint "As-built8"
as_built_joint "As-built9"
as_built_joint "As-built10"
as_built_joint "As-built11"
as_built_joint "As-built12"
as_built_joint "As-built13"
as_built_joint "As-built14"
as_built_joint "As-built15"
work_plane "WorkPlane33" AlongDistance -35 ExtraOffset 0
sketch "PRINT-FIRST-A0-rim Crop Footprint" plane through (0, 0, -35) normal (0, 0, 1) x axis (1, 0, 0)
  line L1 (130, 66.5) -> (55, 66.5)
  line L2 (130, 75) -> (130, 66.5)
  line L3 (55, 75) -> (130, 75)
  line L4 (55, 66.5) -> (55, 75)
  point P1 (0, 0)
  point P2 (55, 66.5)
  point P3 (130, 66.5)
  point P4 (130, 75)
  point P5 (55, 75)
  dimension "d1451" distance P1 P2 = 55 (= "abs(55 mm)")
  dimension "d1452" distance P1 P2 = 66.5 (= "abs(66.5 mm)")
  dimension "d1453" distance P1 P3 = 130 (= "abs(130 mm)")
  dimension "d1454" distance P1 P3 = 66.5 (= "abs(66.5 mm)")
  dimension "d1455" distance P1 P4 = 130 (= "abs(130 mm)")
  dimension "d1456" distance P1 P4 = 75 (= "abs(75 mm)")
  dimension "d1457" distance P1 P5 = 55 (= "abs(55 mm)")
  dimension "d1458" distance P1 P5 = 75 (= "abs(75 mm)")
extrude "Extrude46" sketch "PRINT-FIRST-A0-rim Crop Footprint" along normal blind 70
work_plane "WorkPlane34" AlongDistance 90.1 ExtraOffset 0
sketch "PRINT-FIRST-A0-rim Level Bed Boundary" plane through (63.7103, 63.7103, 0) normal (0.7071, 0.7071, 0) x axis (0, 0, 1)
  line L1 (200, -200) -> (-200, -200)
  line L2 (200, 200) -> (200, -200)
  line L3 (-200, 200) -> (200, 200)
  line L4 (-200, -200) -> (-200, 200)
  line L5 (200, 200) -> (-200, -200)
  point P1 (0, 0)
  point P2 (-200, -200)
  point P3 (200, -200)
  point P4 (200, 200)
  horizontal L1
  vertical L2
  horizontal L3
  vertical L4
  midpoint P1 L5
  dimension "d1463" distance P2 P3 = 400
  dimension "d1464" distance P3 P4 = 400
extrude "Extrude47" sketch "PRINT-FIRST-A0-rim Level Bed Boundary" profile of L1 L2 L3 L4 along normal blind 300
work_plane "WorkPlane35" AlongDistance 66.5 ExtraOffset 0
sketch "PRINT-FIRST-A90-brace Crop Footprint" plane through (0, 0, 66.5) normal (0, 0, 1) x axis (1, 0, 0)
  line L1 (130, -35) -> (48, -35)
  line L2 (130, 35) -> (130, -35)
  line L3 (48, 35) -> (130, 35)
  line L4 (48, -35) -> (48, 35)
  point P1 (0, 0)
  point P2 (48, -35)
  point P3 (130, -35)
  point P4 (130, 35)
  point P5 (48, 35)
  dimension "d1469" distance P1 P2 = 48 (= "abs(48 mm)")
  dimension "d1470" distance P1 P2 = 35 (= "abs(-35 mm)")
  dimension "d1471" distance P1 P3 = 130 (= "abs(130 mm)")
  dimension "d1472" distance P1 P3 = 35 (= "abs(-35 mm)")
  dimension "d1473" distance P1 P4 = 130 (= "abs(130 mm)")
  dimension "d1474" distance P1 P4 = 35 (= "abs(35 mm)")
  dimension "d1475" distance P1 P5 = 48 (= "abs(48 mm)")
  dimension "d1476" distance P1 P5 = 35 (= "abs(35 mm)")
extrude "Extrude48" sketch "PRINT-FIRST-A90-brace Crop Footprint" along normal blind 8.5 bodies "A Housing print (1)"
work_plane "WorkPlane36" AlongDistance 50.1 ExtraOffset 0
sketch "PRINT-FIRST-A90-brace Level Bed Boundary" plane through (35.426, 35.426, 0) normal (0.7071, 0.7071, 0) x axis (0, 0, 1)
  line L1 (200, -200) -> (-200, -200)
  line L2 (200, 200) -> (200, -200)
  line L3 (-200, 200) -> (200, 200)
  line L4 (-200, -200) -> (-200, 200)
  line L5 (200, 200) -> (-200, -200)
  point P1 (0, 0)
  point P2 (-200, -200)
  point P3 (200, -200)
  point P4 (200, 200)
  horizontal L1
  vertical L2
  horizontal L3
  vertical L4
  midpoint P1 L5
  dimension "d1481" distance P2 P3 = 400
  dimension "d1482" distance P3 P4 = 400
extrude "Extrude49" sketch "PRINT-FIRST-A90-brace Level Bed Boundary" profile of L1 L2 L3 L4 along normal blind 300
remove_body "RemoveBody1"
work_plane "WorkPlane28" RotateAngle 90 ExtraOffset 0
work_plane "WorkPlane29" AlongDistance 75 (= "bodyWidth / 2") ExtraOffset 0
sketch "B Driver Pad 1 Slot" plane through (0, -75, 0) normal (0, -1, 0) x axis (-1, 0, 0)
  line L1 (36.5, 28.6274) -> (43, 28.6274)
  line L2 (43, 16.6274) -> (36.5, 16.6274)
  line L3 (36.5, 22.6274) -> (43, 22.6274)
  arc A1 centre (36.5, 22.6274) radius 6 clockwise from (36.5, 16.6274) to (36.5, 28.6274)
  arc A2 centre (43, 22.6274) radius 6 clockwise from (43, 28.6274) to (43, 16.6274)
  point P2 (43, 22.6274)
  point P7 (43, 22.6274)
  point P1 (0, 0)
  point P8 (36.5, 22.6274)
  coincident P2 P7
  tangent L1 A1
  tangent A1 L2
  tangent L2 A2
  tangent L1 A2
  parallel L1 L2
  horizontal L3
  dimension "d1489" distance P1 P2 = 43 (= "Linear Dimension-2")
  dimension "d1490" distance P1 P2 = 22.6274 (= "Linear Dimension-3")
  dimension "d1491" diameter A1 = 12
  dimension "d1492" distance P7 P8 = 6.5
extrude "Extrude49" add sketch "B Driver Pad 1 Slot" profile of L1 A1 L2 A2 no distance stored
sketch "B Driver Pad 2 Slot" plane through (0, -75, 0) normal (0, -1, 0) x axis (-1, 0, 0)
  line L1 (36.5, -16.6274) -> (43, -16.6274)
  line L2 (43, -28.6274) -> (36.5, -28.6274)
  line L3 (36.5, -22.6274) -> (43, -22.6274)
  arc A1 centre (36.5, -22.6274) radius 6 clockwise from (36.5, -28.6274) to (36.5, -16.6274)
  arc A2 centre (43, -22.6274) radius 6 clockwise from (43, -16.6274) to (43, -28.6274)
  point P2 (43, -22.6274)
  point P7 (43, -22.6274)
  point P1 (0, 0)
  point P8 (36.5, -22.6274)
  coincident P2 P7
  tangent L1 A1
  tangent A1 L2
  tangent L2 A2
  tangent L1 A2
  parallel L1 L2
  horizontal L3
  dimension "d1495" distance P1 P2 = 43 (= "Linear Dimension-2")
  dimension "d1496" distance P1 P2 = 22.6274 (= "Linear Dimension-3")
  dimension "d1497" diameter A1 = 12
  dimension "d1498" distance P7 P8 = 6.5
extrude "Extrude50" add sketch "B Driver Pad 2 Slot" profile of L1 A1 L2 A2 no distance stored
sketch "B Driver Pad 3 Slot" plane through (0, -75, 0) normal (0, -1, 0) x axis (-1, 0, 0)
  line L1 (100.5, -16.6274) -> (107, -16.6274)
  line L2 (107, -28.6274) -> (100.5, -28.6274)
  line L3 (100.5, -22.6274) -> (107, -22.6274)
  arc A1 centre (100.5, -22.6274) radius 6 clockwise from (100.5, -28.6274) to (100.5, -16.6274)
  arc A2 centre (107, -22.6274) radius 6 clockwise from (107, -16.6274) to (107, -28.6274)
  point P2 (107, -22.6274)
  point P7 (107, -22.6274)
  point P1 (0, 0)
  point P8 (100.5, -22.6274)
  coincident P2 P7
  tangent L1 A1
  tangent A1 L2
  tangent L2 A2
  tangent L1 A2
  parallel L1 L2
  horizontal L3
  dimension "d1501" distance P1 P2 = 107 (= "Linear Dimension-2")
  dimension "d1502" distance P1 P2 = 22.6274 (= "Linear Dimension-3")
  dimension "d1503" diameter A1 = 12
  dimension "d1504" distance P7 P8 = 6.5
extrude "Extrude51" add sketch "B Driver Pad 3 Slot" profile of L1 A1 L2 A2 no distance stored
sketch "B Driver Pad 4 Slot" plane through (0, -75, 0) normal (0, -1, 0) x axis (-1, 0, 0)
  line L1 (100.5, 28.6274) -> (107, 28.6274)
  line L2 (107, 16.6274) -> (100.5, 16.6274)
  line L3 (100.5, 22.6274) -> (107, 22.6274)
  arc A1 centre (100.5, 22.6274) radius 6 clockwise from (100.5, 16.6274) to (100.5, 28.6274)
  arc A2 centre (107, 22.6274) radius 6 clockwise from (107, 28.6274) to (107, 16.6274)
  point P2 (107, 22.6274)
  point P7 (107, 22.6274)
  point P1 (0, 0)
  point P8 (100.5, 22.6274)
  coincident P2 P7
  tangent L1 A1
  tangent A1 L2
  tangent L2 A2
  tangent L1 A2
  parallel L1 L2
  horizontal L3
  dimension "d1507" distance P1 P2 = 107 (= "Linear Dimension-2")
  dimension "d1508" distance P1 P2 = 22.6274 (= "Linear Dimension-3")
  dimension "d1509" diameter A1 = 12
  dimension "d1510" distance P7 P8 = 6.5
extrude "Extrude52" add sketch "B Driver Pad 4 Slot" profile of L1 A1 L2 A2 no distance stored
work_plane "WorkPlane30" AlongDistance -35 ExtraOffset 0
sketch "B Mount Driver Axes" plane through (-24.7487, -24.7487, 0) normal (0.7071, 0.7071, 0) x axis (0, 0, 1)
  circle C1 centre (22.6274, 22.6274) radius 2.5
  circle C2 centre (-22.6274, 22.6274) radius 2.5
  circle C3 centre (-22.6274, -22.6274) radius 2.5
  circle C4 centre (22.6274, -22.6274) radius 2.5
  point P1 (0, 0)
  point P2 (22.6274, 22.6274)
  point P3 (-22.6274, 22.6274)
  point P4 (-22.6274, -22.6274)
  point P5 (22.6274, -22.6274)
  dimension "d1515" distance P1 P2 = 22.6274 (= "abs(mountCircle / ( 2 * sqrt(2) ))")
  dimension "d1516" distance P1 P2 = 22.6274 (= "abs(mountCircle / ( 2 * sqrt(2) ))")
  dimension "d1517" diameter C1 = 5 (= "driverPort")
  dimension "d1518" distance P1 P3 = 22.6274 (= "abs(-mountCircle / ( 2 * sqrt(2) ))")
  dimension "d1519" distance P1 P3 = 22.6274 (= "abs(mountCircle / ( 2 * sqrt(2) ))")
  dimension "d1520" diameter C2 = 5 (= "driverPort")
  dimension "d1521" distance P1 P4 = 22.6274 (= "abs(-mountCircle / ( 2 * sqrt(2) ))")
  dimension "d1522" distance P1 P4 = 22.6274 (= "abs(-mountCircle / ( 2 * sqrt(2) ))")
  dimension "d1523" diameter C3 = 5 (= "driverPort")
  dimension "d1524" distance P1 P5 = 22.6274 (= "abs(mountCircle / ( 2 * sqrt(2) ))")
  dimension "d1525" distance P1 P5 = 22.6274 (= "abs(-mountCircle / ( 2 * sqrt(2) ))")
  dimension "d1526" diameter C4 = 5 (= "driverPort")
extrude "Extrude53" cut sketch "B Mount Driver Axes" no distance stored
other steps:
base_feature "Base Feature1" bodies "A Housing print"
base_feature "Base Feature1" bodies "B Moving Body print"
create_component "CreateComponent1"
reparent_decal "ReparentDecal1"
remove_body "RemoveBody1"
create_component "CreateComponent2"
reparent_decal "ReparentDecal2"
remove_body "RemoveBody2"
create_component "CreateComponent3"
create_component "CreateComponent4"
create_component "CreateComponent5"
create_component "CreateComponent6"
create_component "CreateComponent7"
create_component "CreateComponent8"
create_component "CreateComponent9"
create_component "CreateComponent10"
create_component "CreateComponent11"
create_component "CreateComponent12"
create_component "CreateComponent13"
create_component "CreateComponent14"
create_component "CreateComponent15"
create_component "CreateComponent16"
named bodies: "A Housing print", "B Moving Body print", "A Housing print (1)"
